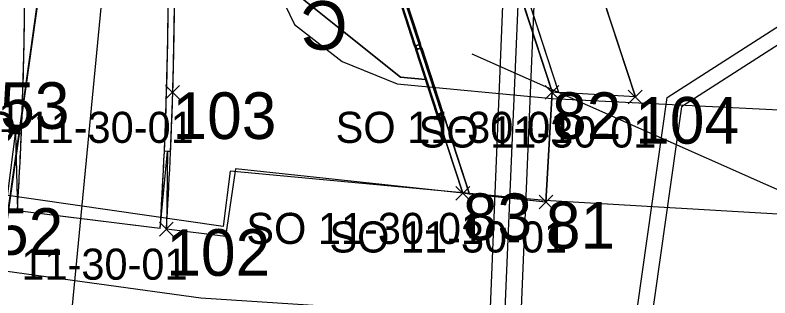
# Model space of a CAD drawing. Extents: x -728800 to -728100, y -1073200 to -1072700.
# Drawn here: x -728501.75 to -728492.02, y -1073043.64 to -1073040.01 of the extents above; entities that cross this region are included whole.
import ezdxf

# ---------------------------------------------------------------- set-up
doc = ezdxf.new("R2010")
doc.units = 0
for name, color, linetype in [('_NOR-návrh tenká', 7, 'Continuous'), ('_NOR-šraf_+-0', 7, 'Continuous'), ('_NOR-šraf_+12', 7, 'Continuous'), ('_NOR-šraf_+6', 7, 'Continuous'), ('_NOR-šraf_chodník', 7, 'Continuous'), ('_NOR-šraf_zeleň', 7, 'Continuous'), ('A1_OBVOD Spravy železnic', 7, 'Continuous'), ('A2_OBVOD STAVBY', 7, 'Continuous'), ('B1_body_poloha', 7, 'Continuous'), ('B2_body_číslo', 7, 'Continuous'), ('B3_body_popiska', 7, 'Continuous'), ('B6_JŽM', 7, 'Continuous'), ('KOS_kabelová trasa', 7, 'Continuous'), ('KOS_nové prvky PZZ', 7, 'Continuous'), ('ZA_01_Trvalý_pro_SŽDC_dle_UMVZST', 7, 'Continuous'), ('ZA_02_Dočasný_do_1_roku', 7, 'Continuous'), ('ZZZ_popisky', 7, 'Continuous')]:
    doc.layers.add(name, color=color, linetype=linetype)

msp = doc.modelspace()

# ---------------------------------------------------------------- linework, layer by layer
at = {"layer": '_NOR-návrh tenká'}
for p, q in [((-728494.83, -1073040.995), (-728496.6299, -1073035.4928)), ((-728494.7442, -1073041.0001), (-728496.5539, -1073035.4679)), ((-728495.8946, -1073042.3079), (-728497.9796, -1073035.9343)), ((-728495.9818, -1073042.2985), (-728498.0556, -1073035.9592)), ((-728496.2919, -1073041.3024), (-728498.0175, -1073036.0275)), ((-728496.2444, -1073041.2869), (-728497.97, -1073036.0119)), ((-728493.7572, -1073041.0582), (-728495.3935, -1073036.0563)), ((-728501.4824, -1073048.6764), (-728500.3754, -1073037.1911)), ((-728494.91, -1073042.414), (-728494.83, -1073040.995)), ((-728501.8676, -1073042.5064), (-728501.7419, -1073041.5296)), ((-728501.8169, -1073041.5296), (-728501.6668, -1073041.5296)), ((-728501.7419, -1073041.5296), (-728501.7184, -1073042.5247)), ((-728499.8789, -1073042.7498), (-728499.785, -1073041.7592)), ((-728499.745, -1073041.761), (-728499.825, -1073041.7574)), ((-728499.785, -1073041.7592), (-728499.7994, -1073042.7595)), ((-728494.91, -1073042.414), (-728495.9818, -1073042.2985))]:
    msp.add_line(p, q, dxfattribs=at)
for centre in [(-728496.5557, -1073040.4155), (-728496.2681, -1073041.2946)]:
    msp.add_circle(centre, 0.025, dxfattribs=at)
for radius, start in [(52, 356.34097), (52.08, 356.33586), (50.15, 356.46353)]:
    msp.add_arc((-728551.7729, -1073039.4312), radius, start, 0.20859, dxfattribs=at)
at = {"layer": '_NOR-šraf_+-0'}
msp.add_lwpolyline([(-728494.83, -1073040.995), (-728494.7442, -1073041.0001), (-728496.5539, -1073035.4679), (-728496.6299, -1073035.4928), (-728494.83, -1073040.995), (-728494.83, -1073040.995)], dxfattribs=at)
at = {"layer": '_NOR-šraf_+12'}
msp.add_lwpolyline([(-728501.6668, -1073041.5296), (-728501.7419, -1073041.5296), (-728501.8169, -1073041.5296)], dxfattribs=at)
msp.add_arc((-728551.7729, -1073039.4312), 50.15, 357.602, 0.20859, dxfattribs=at)
at = {"layer": '_NOR-šraf_+6'}
for p, q in [((-728496.6015, -1073040.4041), (-728496.8736, -1073039.5725)), ((-728496.7975, -1073039.5476), (-728496.5255, -1073040.3793)), ((-728496.5255, -1073040.3793), (-728496.6015, -1073040.4041)), ((-728496.586, -1073040.4517), (-728496.5099, -1073040.4268)), ((-728496.3139, -1073041.2833), (-728496.586, -1073040.4517)), ((-728496.5099, -1073040.4268), (-728496.2379, -1073041.2584)), ((-728496.2379, -1073041.2584), (-728496.3139, -1073041.2833)), ((-728496.2984, -1073041.3308), (-728496.2223, -1073041.3059)), ((-728495.9818, -1073042.2985), (-728496.2984, -1073041.3308)), ((-728496.2223, -1073041.3059), (-728495.8946, -1073042.3079)), ((-728499.785, -1073041.7592), (-728499.825, -1073041.7574)), ((-728499.745, -1073041.761), (-728499.785, -1073041.7592)), ((-728495.8946, -1073042.3079), (-728495.9818, -1073042.2985))]:
    msp.add_line(p, q, dxfattribs=at)
msp.add_lwpolyline([(-728499.745, -1073041.761), (-728499.785, -1073041.7592), (-728499.825, -1073041.7574)], dxfattribs=at)
for centre, radius, start, end in [((-728551.7729, -1073039.4312), 52, 357.43603, 0.20859), ((-728551.7729, -1073039.4312), 52.08, 357.43603, 0.20859), ((-728551.7729, -1073039.4312), 52.08, 358.88417, 359.9006), ((-728551.7729, -1073039.4312), 52, 358.85342, 359.87159), ((-728551.7732, -1073039.4312), 52.0004, 358.79505, 358.85342), ((-728551.7729, -1073039.4312), 52.08, 357.80277, 358.8259), ((-728551.7727, -1073039.4312), 52.0798, 358.8259, 358.88417), ((-728551.7729, -1073039.4312), 52, 357.77014, 358.79505), ((-728551.7732, -1073039.4312), 52.0003, 357.71137, 357.77014), ((-728551.7729, -1073039.4312), 52.08, 357.43603, 357.7441), ((-728551.7726, -1073039.4313), 52.0797, 357.7441, 357.80277), ((-728551.7729, -1073039.4312), 52, 357.43603, 357.71137)]:
    msp.add_arc(centre, radius, start, end, dxfattribs=at)
at = {"layer": '_NOR-šraf_chodník'}
for p, q in [((-728496.6472, -1073035.44), (-728494.83, -1073040.995)), ((-728495.8946, -1073042.3079), (-728497.9906, -1073035.9006)), ((-728494.83, -1073040.995), (-728494.91, -1073042.414)), ((-728494.91, -1073042.414), (-728495.8946, -1073042.3079)), ((-728499.9874, -1073042.7365), (-728501.7184, -1073042.5247)), ((-728499.8789, -1073042.7498), (-728499.9874, -1073042.7365))]:
    msp.add_line(p, q, dxfattribs=at)
msp.add_lwpolyline([(-728499.8789, -1073042.7498), (-728499.9874, -1073042.7365), (-728501.1678, -1073042.5921), (-728501.7184, -1073042.5247)], dxfattribs=at)
for radius, start, end in [(52, 356.34097, 0.20859), (52, 357.43603, 0.20859), (50.15, 356.46353, 0.20859), (50.15, 357.602, 0.20859), (50.15, 356.46353, 357.602), (52, 356.34097, 357.43603)]:
    msp.add_arc((-728551.7729, -1073039.4312), radius, start, end, dxfattribs=at)
at = {"layer": '_NOR-šraf_zeleň'}
for p, q in [((-728494.7442, -1073041.0001), (-728496.5539, -1073035.4679)), ((-728495.3935, -1073036.0563), (-728493.7572, -1073041.0582)), ((-728498.297, -1073039.593), (-728496.785, -1073040.803)), ((-728496.785, -1073040.803), (-728496.4606, -1073040.8349)), ((-728496.4606, -1073040.8349), (-728495.9818, -1073042.2985)), ((-728493.7572, -1073041.0582), (-728494.7442, -1073041.0001)), ((-728498.908, -1073041.983), (-728499.0357, -1073042.853)), ((-728495.9818, -1073042.2985), (-728498.908, -1073041.983)), ((-728499.0357, -1073042.853), (-728499.7994, -1073042.7595))]:
    msp.add_line(p, q, dxfattribs=at)
msp.add_lwpolyline([(-728496.4606, -1073040.8349), (-728496.785, -1073040.803), (-728498.297, -1073039.593), (-728497.8284, -1073037.3593), (-728497.826, -1073037.348), (-728497.7942, -1073037.3251), (-728497.6441, -1073037.217), (-728496.4606, -1073040.8349)], dxfattribs=at)
msp.add_arc((-728551.7729, -1073039.4312), 52.08, 356.33586, 0.20859, dxfattribs=at)
at = {"layer": 'A1_OBVOD Spravy železnic'}
msp.add_lwpolyline([(-728503.24, -1073052.34), (-728501.9463, -1073043.2931), (-728501.19, -1073037.94), (-728499.78, -1073032.61), (-728497.54, -1073030.15), (-728493.68, -1073027.94), (-728443.97, -1073014.59), (-728443.68, -1073014.51), (-728441.09, -1073023.23), (-728428.92, -1073019.94), (-728429.82, -1073016.43), (-728427.49, -1073015.84), (-728421.24, -1073014.23), (-728422.34, -1073010.27), (-728422.77, -1073008.34), (-728418.21, -1073007), (-728380.57, -1072997.2), (-728343.1, -1072987.57), (-728330.49, -1072984.52), (-728326.79, -1072988.95)], dxfattribs=at)
at = {"layer": 'A2_OBVOD STAVBY'}
msp.add_lwpolyline([(-728488.873, -1073026.674), (-728487.617, -1073033.5782), (-728488.4182, -1073038.141), (-728493.1643, -1073041.1869), (-728493.9181, -1073046.5148)], dxfattribs=at)
at = {"layer": 'B1_body_poloha'}
for p, q in [((-728499.8084, -1073040.9116), (-728499.6316, -1073041.0884)), ((-728499.8084, -1073041.0884), (-728499.6316, -1073040.9116)), ((-728494.9184, -1073040.9116), (-728494.7416, -1073041.0884)), ((-728494.9184, -1073041.0884), (-728494.7416, -1073040.9116)), ((-728493.8484, -1073040.9716), (-728493.6716, -1073041.1484)), ((-728493.8484, -1073041.1484), (-728493.6716, -1073040.9716)), ((-728496.0684, -1073042.2116), (-728495.8916, -1073042.3884)), ((-728496.0684, -1073042.3884), (-728495.8916, -1073042.2116)), ((-728494.9984, -1073042.3216), (-728494.8216, -1073042.4984)), ((-728494.9984, -1073042.4984), (-728494.8216, -1073042.3216)), ((-728499.8884, -1073042.6716), (-728499.7116, -1073042.8484)), ((-728499.8884, -1073042.8484), (-728499.7116, -1073042.6716))]:
    msp.add_line(p, q, dxfattribs=at)
at = {"layer": 'B2_body_číslo'}
for p, q in [((-728499.72, -1073041), (-728499.72, -1073041)), ((-728494.83, -1073041), (-728494.83, -1073041)), ((-728493.76, -1073041.06), (-728493.76, -1073041.06)), ((-728495.98, -1073042.3), (-728495.98, -1073042.3)), ((-728494.91, -1073042.41), (-728494.91, -1073042.41)), ((-728499.8, -1073042.76), (-728499.8, -1073042.76))]:
    msp.add_line(p, q, dxfattribs=at)
at = {"layer": 'B6_JŽM'}
for points in [[(-728300.8085, -1073024.3545), (-728320.8, -1073026.914), (-728374.008, -1073033.722), (-728429.095, -1073040.747), (-728461.932, -1073044.273), (-728481.199, -1073044.815), (-728499.353, -1073043.648), (-728506.01, -1073042.737), (-728514.574, -1073041.329), (-728535.848, -1073035.998), (-728561.353, -1073026.113), (-728583.963, -1073013.524), (-728603.757, -1072998.891), (-728619.185, -1072984.418), (-728634.193, -1072966.825), (-728646.078, -1072949.194), (-728656.182, -1072930.072), (-728664.987, -1072910.227), (-728668.627, -1072901.808), (-728681.252, -1072876.016), (-728691.886, -1072859.663)], [(-728496.482, -1073035.776), (-728497.4937, -1073036.6437), (-728498.316, -1073037.996), (-728498.5283, -1073038.6029), (-728498.459, -1073039.486), (-728498.149, -1073040.1285), (-728497.5331, -1073040.6035), (-728496.825, -1073040.892), (-728494.827, -1073041.079), (-728486.835, -1073041.479), (-728486.937, -1073042.858), (-728494.923, -1073042.391), (-728498.977, -1073042.014), (-728499.069, -1073042.727), (-728513.553, -1073040.642)]]:
    msp.add_lwpolyline(points, dxfattribs=at)
at = {"layer": 'KOS_kabelová trasa'}
for p, q in [((-728495.7665, -1073047.15), (-728495.3938, -1073038.2172)), ((-728495.3669, -1073047.1667), (-728494.9941, -1073038.2339))]:
    msp.add_line(p, q, dxfattribs=at)
msp.add_lwpolyline([(-728499.6877, -1073048.4364), (-728495.6152, -1073048.0137), (-728495.1842, -1073037.964)], dxfattribs=at)
at = {"layer": 'ZA_01_Trvalý_pro_SŽDC_dle_UMVZST'}
msp.add_lwpolyline([(-728502.83, -1073049.48), (-728501.19, -1073037.94), (-728500.7194, -1073036.1609), (-728510.3267, -1073035.4653), (-728510.22, -1073036.28), (-728509.42, -1073042.19), (-728509.9, -1073046.86), (-728517.0095, -1073045.1202), (-728517.3822, -1073047.3107), (-728510.2456, -1073048.3747)], dxfattribs=at)
at = {"layer": 'ZA_02_Dočasný_do_1_roku'}
for points in [[(-728494.1165, -1073046.4898), (-728493.3495, -1073041.0682), (-728488.6, -1073038.02), (-728487.8202, -1073033.5788), (-728489.0681, -1073026.7185)], [(-728493.1267, -1073026.8514), (-728494.629, -1073027.3499), (-728496.2837, -1073028.1637), (-728498.4547, -1073029.8063), (-728499.6945, -1073031.1155), (-728500.7898, -1073032.7007), (-728501.6149, -1073034.32), (-728501.8023, -1073034.8884), (-728501.5592, -1073036.1001), (-728500.7194, -1073036.1609), (-728499.78, -1073032.61), (-728497.54, -1073030.15), (-728493.68, -1073027.94), (-728491.3018, -1073027.3013), (-728488.39, -1073034.38), (-728493.51, -1073034.35), (-728493.84, -1073039.37), (-728501.19, -1073037.94), (-728502.0422, -1073043.9717)]]:
    msp.add_lwpolyline(points, dxfattribs=at)
at = {"layer": 'ZZZ_popisky'}
msp.add_lwpolyline([(-728495.8627, -1073040.5055), (-728482.3001, -1073046.5165), (-728480.9705, -1073043.5167)], dxfattribs=at)

# ---------------------------------------------------------------- texts
at = {"layer": 'B2_body_číslo'}
for s, p in [('53', (-728501.94, -1073041.47)), ('103', (-728499.72, -1073041.6)), ('82', (-728494.83, -1073041.6)), ('104', (-728493.76, -1073041.66)), ('83', (-728495.98, -1073042.9)), ('81', (-728494.91, -1073043.01)), ('52', (-728502.02, -1073043.09)), ('102', (-728499.8, -1073043.36))]:
    msp.add_text(s, height=0.6, dxfattribs=at).set_placement(p)
at = {"layer": 'B3_body_popiska'}
for p in [(-728504.7287, -1073041.52), (-728502.5087, -1073041.65), (-728497.6187, -1073041.65), (-728496.5487, -1073041.71), (-728498.7687, -1073042.95), (-728497.6987, -1073043.06), (-728502.5887, -1073043.41)]:
    msp.add_text('SO 11-30-01', height=0.4, dxfattribs=at).set_placement(p)
at = {"layer": 'KOS_nové prvky PZZ'}
msp.add_text('C', height=0.625, rotation=180, dxfattribs=at).set_placement((-728497.4635, -1073039.8255))

doc.saveas('drawing.dxf')
